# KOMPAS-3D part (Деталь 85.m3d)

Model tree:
1. Эскиз:1
2. Операция вращения:1
     Угол 1 = 360
3. Эскиз:2
4. Вырезать элемент выдавливания:1
     Расстояние 1 = 32.6
5. Эскиз:3
6. Вырезать элемент выдавливания:2
     Расстояние 1 = 32.6
7. Фаска:1
     Угол = 45; Длина 1 = 1.5; Длина 2 = 1.5
8. Условное изображение резьбы:1  (labels: ..\..\..\..\..\ASCON\KOMPAS\Sys\Thread\cil1_24705-2004.xml; C:\ASCON\KOMPAS\Sys\Thread\cil1_24705-2004.xml; M16x0.75)
     Шаг резьбы = 0.75; Номинальный диаметр резьбы = 16
9. Подгонка:1
10. Эскиз:4
11. Вырезать элемент выдавливания:3  (labels: СамГТУ 85)
     Расстояние 1 = 32.6

Referenced files in C:\ASCON\KOMPAS\Sys\Thread\: cil1_24705-2004.xml
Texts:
  СамГТУ 85
  СЧ25  ГОСТ 1412-85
